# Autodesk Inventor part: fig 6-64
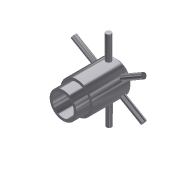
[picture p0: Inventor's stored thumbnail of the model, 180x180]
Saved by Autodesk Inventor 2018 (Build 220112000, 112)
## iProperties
Shininess: 77.0
Angle Display Precision: 2
Document Length Units: 11269
Document Angle Units: 11279
Document Time Units: 11290
Document Mass Units: 11283
Document Length Units Precision: 3
Document Angle Units Precision: 2
Compacted: True
Created: 2001-12
Part Number: fig 6-64
Document SubType Name: Modeling
Designer: Renu Muthoo
Density: 1 g/cm^3
Material: Generic
Appearance: Metal-AL-6061 (Polished)
Density: 0.0
Volumn: 0.0
Area: 0.0
PropertySet Name: Model Information
Control State: 0
Master: False
Checked Out: False
Author: Renu Muthoo
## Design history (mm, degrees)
sketch "Sketch2"
  geometry: L1 (-9.573, -4.327)-(-9.573, -5.327); L2 (-9.573, -5.327)-(-4.573, -5.327); L3 (-4.573, -5.327)-(-4.573, -6.327); L4 (-4.573, -6.327)-(9.427, -6.327); L5 (9.427, -6.327)-(10.427, -5.327); L6 (10.427, -5.327)-(10.427, -4.327); L7 (10.427, -4.327)-(-9.573, -4.327); L8 (-13.687, -0.327)-(14, -0.327)
  constraints: 16 end point, 5 parallel, 1 perpendicular, 1 vertical
  dimensions: "d9" = 20 distance of L6.end L1.start; "d10" = 5 distance of L1.end L2.end; "d11" = 12 diameter of L4 L8; "d12" = 10 diameter of L2 L8; "d13" = 8 diameter of L7 L8; "d14" = 45 deg angle of L5 L4; "d15" = 1 horizontal distance of L5.end L4.end
revolve "Revolution2" sketch "Sketch2" stored, may be unused: angle "d16" = 90 deg
workplane "Work Plane1"
workplane "Work Plane2"
sketch "Sketch3"
  geometry: L1 (-4, 8)-(4, 8) reference; C1 r 1 at (-0.098, 5)
  constraints: 1 centre point
  dimensions: "d18" = 3 distance from line of L1 C1.centre; "d19" = 2 diameter of C1
extrude "Extrusion1" join sketch "Sketch3" distance "d20" = 10; taper "d21" = 0 deg
pattern_circular "Circular Pattern3" dims angle "d29" = 360 deg
body "Solid1"
other parameters: "d17" = -1
